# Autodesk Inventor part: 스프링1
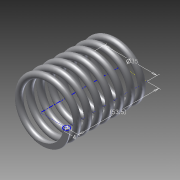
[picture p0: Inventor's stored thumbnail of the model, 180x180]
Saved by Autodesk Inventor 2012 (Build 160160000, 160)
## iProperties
Created: 2014-12
Part Number: 스프링1
Material: Default
Document SubType Name: Modeling
Designer: Owner
Mass: 10.1805 g
Surface Area: 103 cm^2
Volume: 10.1805 cm^3
Density: 1 g/cm^3
Author: Owner
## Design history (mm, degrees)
sketch "스케치1"
  geometry: L1 (0, 0)-(17.5, 0); L2 (17.5, 0)-(17.5, 48.5); L3 (17.5, 48.5)-(0, 48.5); L4 (0, 48.5)-(0, 0); C1 r 2 at (17.5, 0)
  constraints: 8 end point, 2 parallel, 1 centre point, 1 coincident, 1 horizontal, 1 perpendicular
  dimensions: "d0" = 4 diameter of C1; "d1" = 35 diameter of L2 L4; "d2" = 48.5 distance of L1.end L2.end (derived)
feature "코일1" pitch "d3" = 10; turns "d5" = 7.5; dims "d4" = 48.5 (= d2), "d6" = 0, angle "d7" = 90 deg, angle "d8" = 90 deg, "d9" = 0, "d10" = 0
sketch "스케치2"
  geometry: L1 (-19.5, 0)-(-15.5, 0) reference; 1 further point
  constraints: 1 horizontal alignment
extrude "돌출1" cut sketch "스케치2" stored distance "d11" = 10; taper "d12" = 0 deg
node "작업 평면1"
sketch "스케치3"
  geometry: L1 (15.5, 0)-(19.5, 0) reference; 1 further point
  constraints: 1 horizontal alignment
extrude "돌출2" cut sketch "스케치3" stored distance "d13" = 10; taper "d14" = 0 deg
node "솔리드1"
node "절단 모서리 투영1"
node "절단 모서리 투영2"
